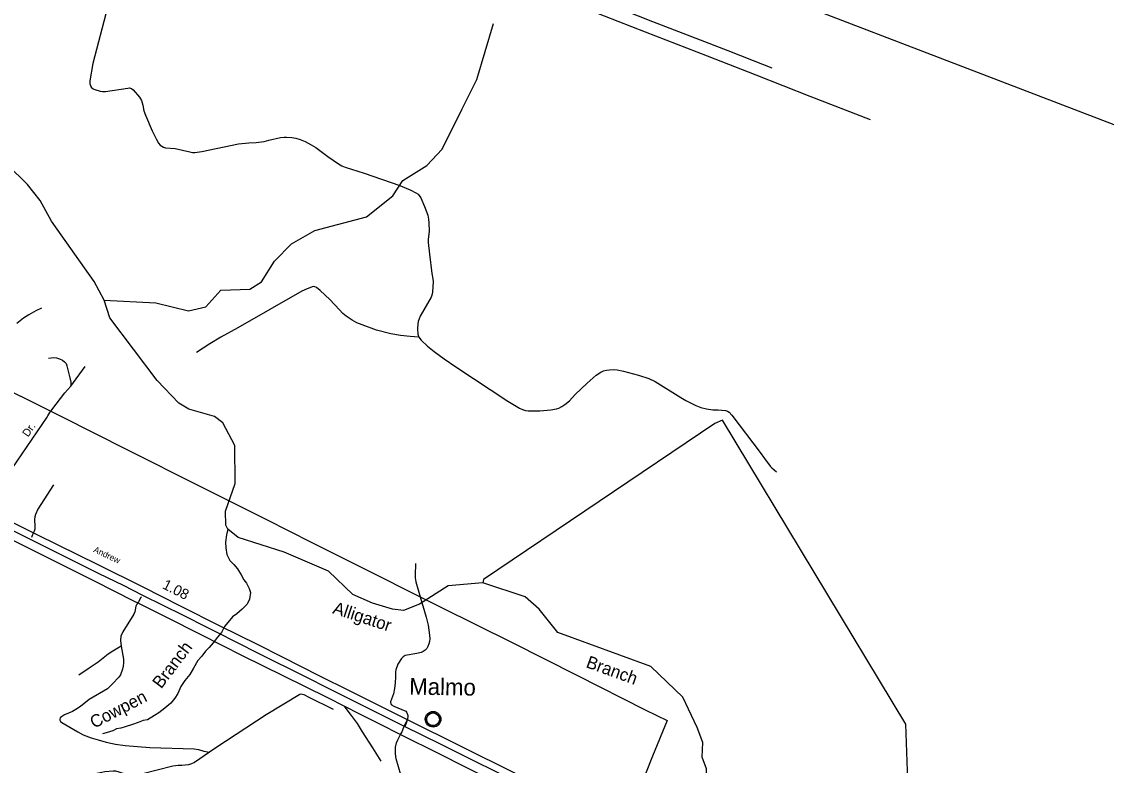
# Model space of a CAD drawing. Extents: x 2225501 to 2309677, y 165449 to 227696.
# Drawn here: x 2267922 to 2280990, y 188364 to 197321 of the extents above; entities that cross this region are included whole.
import ezdxf

# ---------------------------------------------------------------- set-up
doc = ezdxf.new("R2010")
doc.units = 0
for name, color, linetype in [('Black Area Fill Shapes', 7, 'Continuous'), ('MARK ENDS WORD SYMBOL CELL', 7, 'Continuous'), ('Old_Level_3', 7, 'Continuous'), ('Old_Level_33', 7, 'Continuous'), ('Old_Level_41', 7, 'Continuous'), ('Old_Level_46', 7, 'Continuous'), ('P_HYD_Diversion_Ditch_Label', 7, 'Continuous'), ('P_HYD_Drop_Inlet_Grate_3_Narrow_Slot_and_Sag_Grates_840_22_Type_A_60_Dia-Top_CELL', 7, 'Continuous'), ('Prop Support', 7, 'Continuous'), ('Raster_Level_0', 7, 'Continuous'), ('Scratch_Level_1', 7, 'Continuous'), ('Scratch_Level_2', 7, 'Continuous'), ('Typical Terminator CELL', 7, 'Continuous')]:
    doc.layers.add(name, color=color, linetype=linetype)

msp = doc.modelspace()

# ---------------------------------------------------------------- linework, layer by layer
at = {"layer": 'Black Area Fill Shapes'}
for points in [[(2268889, 199744), (2269360, 199561), (2269931, 199338), (2270754, 199020), (2271590, 198697), (2272090, 198499), (2272866, 198202), (2273728, 197866), (2274609, 197521), (2275433, 197198), (2276180, 196909), (2276769, 196681), (2277420, 196425), (2278147, 196143)], [(2267482, 193022), (2267541, 192993), (2268273, 192629)], [(2268273, 192629), (2268402, 192565), (2269187, 192170), (2270067, 191726), (2270870, 191325), (2271409, 191054), (2272091, 190712), (2272724, 190395)], [(2272724, 190395), (2272974, 190270), (2273833, 189844), (2274610, 189451), (2275435, 189034), (2275700, 188902)], [(2272255, 188416), (2272153, 188575), (2272027, 188769), (2271966, 188867), (2271895, 188964), (2271842, 189033), (2271812, 189075)]]:
    msp.add_lwpolyline(points, dxfattribs=at)
at = {"layer": 'Old_Level_3'}
for p, q in [((2272696, 193558), (2272708, 193522)), ((2268512, 192932), (2268686, 193169)), ((2268046, 191122), (2268040, 191107)), ((2268066, 191170), (2268046, 191122)), ((2269329, 190335), (2269320, 190322)), ((2269359, 190384), (2269329, 190335)), ((2269364, 190393), (2269359, 190384)), ((2272549, 188860), (2272540, 188839)), ((2272554, 188873), (2272549, 188860)), ((2272570, 188925), (2272554, 188873))]:
    msp.add_line(p, q, dxfattribs=at)
for points in [[(2268934, 197416), (2268780, 196819), (2268744, 196609), (2268744, 196573), (2268749, 196551), (2268760, 196532), (2268783, 196513), (2268802, 196503), (2268866, 196483), (2268896, 196479), (2268930, 196480), (2269199, 196522), (2269220, 196523), (2269245, 196517), (2269266, 196502), (2269341, 196411), (2269364, 196374), (2269381, 196316), (2269394, 196248), (2269413, 196194), (2269494, 196008), (2269542, 195909), (2269571, 195857), (2269591, 195833), (2269630, 195810), (2269654, 195802), (2269770, 195795), (2269947, 195752), (2269979, 195746), (2270009, 195747), (2270093, 195756), (2270535, 195849), (2270657, 195862), (2270747, 195868), (2270845, 195879), (2270900, 195895), (2271040, 195925), (2271084, 195931), (2271112, 195932), (2271176, 195926), (2271224, 195918), (2271278, 195903), (2271336, 195880), (2271411, 195839), (2271464, 195808), (2271612, 195699), (2271739, 195609), (2271778, 195586), (2271818, 195570), (2272047, 195498), (2272478, 195348), (2272612, 195293), (2272672, 195261), (2272698, 195242), (2272731, 195200), (2272776, 195097), (2272814, 194992), (2272825, 194941), (2272828, 194900), (2272830, 194800), (2272819, 194698), (2272820, 194662), (2272835, 194520), (2272865, 194287), (2272875, 194225), (2272878, 194187), (2272872, 194069), (2272869, 194041), (2272857, 194002), (2272723, 193776), (2272699, 193710), (2272693, 193682), (2272689, 193620), (2272696, 193558)], [(2272708, 193522), (2272601, 193529), (2272488, 193540), (2272368, 193560), (2272197, 193607), (2272023, 193668), (2271961, 193695), (2271902, 193728), (2271832, 193776), (2271793, 193808), (2271750, 193851), (2271636, 193975), (2271520, 194085), (2271472, 194118), (2271455, 194126), (2271432, 194130), (2271360, 194104), (2271299, 194075), (2270526, 193634), (2270322, 193522), (2270187, 193442), (2270027, 193337)], [(2268161, 193870), (2268092, 193839), (2268007, 193792), (2267942, 193749), (2267863, 193685)], [(2272689, 193620), (2272696, 193558)], [(2272708, 193522), (2272737, 193484), (2272810, 193414), (2272893, 193347), (2273014, 193259), (2273152, 193164), (2273780, 192752), (2273921, 192666), (2273957, 192649), (2273992, 192638), (2274026, 192633), (2274164, 192635), (2274297, 192648), (2274365, 192659), (2274393, 192667), (2274429, 192686), (2274466, 192709), (2274522, 192753), (2274592, 192829), (2274734, 192967), (2274844, 193063), (2274900, 193101), (2274933, 193115), (2274967, 193123), (2275005, 193128), (2275057, 193130), (2275095, 193126), (2275173, 193111), (2275353, 193062), (2275477, 193022), (2275554, 192988), (2275864, 192793), (2275926, 192758), (2276043, 192698), (2276103, 192675), (2276175, 192657), (2276250, 192648), (2276314, 192645), (2276402, 192637), (2276428, 192629), (2276446, 192617), (2276479, 192583), (2276819, 192132), (2276870, 192061), (2276941, 191968), (2276962, 191946), (2277015, 191901)], [(2268244, 193270), (2268308, 193277), (2268343, 193272), (2268378, 193262), (2268415, 193245), (2268437, 193225), (2268456, 193203), (2268466, 193178), (2268502, 193032), (2268512, 192981), (2268512, 192932)], [(2268273, 192629), (2268338, 192715), (2268442, 192849), (2268512, 192932)], [(2268307, 191743), (2268118, 191450), (2268087, 191385), (2268080, 191359), (2268076, 191331), (2268082, 191237), (2268079, 191209), (2268073, 191185), (2268066, 191170)], [(2272668, 190795), (2272663, 190650), (2272663, 190623), (2272672, 190575), (2272724, 190395)], [(2269320, 190322), (2269310, 190306), (2269299, 190280), (2269284, 190212), (2269275, 190186), (2269142, 189973), (2269117, 189919), (2269112, 189869), (2269121, 189801)], [(2272724, 190395), (2272795, 190147), (2272819, 190054), (2272837, 189930), (2272838, 189886), (2272836, 189856), (2272829, 189828), (2272816, 189796), (2272802, 189773), (2272784, 189753), (2272761, 189735), (2272737, 189724), (2272681, 189711), (2272541, 189687), (2272520, 189672), (2272498, 189650), (2272455, 189582), (2272428, 189515), (2272425, 189489), (2272426, 189431), (2272421, 189359), (2272412, 189290), (2272401, 189226), (2272367, 189130), (2272365, 189120), (2272368, 189104), (2272376, 189092), (2272404, 189076), (2272549, 189016), (2272557, 189005), (2272571, 188977), (2272574, 188965), (2272575, 188953), (2272570, 188925)], [(2269121, 189801), (2269148, 189644), (2269150, 189597), (2269146, 189558), (2269138, 189521), (2269111, 189455), (2269092, 189425), (2269017, 189345), (2268954, 189286), (2268734, 189158), (2268630, 189072), (2268576, 189035), (2268535, 189013), (2268437, 188971), (2268402, 188950), (2268386, 188936), (2268382, 188919), (2268383, 188906), (2268391, 188890), (2268405, 188878), (2268597, 188767), (2268664, 188733), (2268757, 188697), (2268843, 188670), (2268941, 188644), (2269054, 188620), (2269168, 188604), (2269464, 188579), (2269998, 188562), (2270051, 188553), (2270118, 188534), (2270185, 188522)], [(2269121, 189801), (2269018, 189741), (2268965, 189702), (2268844, 189606), (2268736, 189536), (2268611, 189450)], [(2271679, 189038), (2271384, 189181), (2271324, 189214), (2271287, 189221), (2271272, 189217), (2270868, 188972), (2270261, 188575), (2270185, 188522)], [(2275700, 188902), (2275521, 188473), (2275352, 188050), (2275276, 187849), (2275210, 187691), (2275178, 187620)], [(2270185, 188522), (2270002, 188399), (2269966, 188382), (2269933, 188370), (2269852, 188360), (2269806, 188361), (2269743, 188354), (2269364, 188259), (2269312, 188248), (2269271, 188244), (2269236, 188243), (2269204, 188247), (2269098, 188282), (2269058, 188292), (2269023, 188292), (2268922, 188285), (2268888, 188277), (2268768, 188255), (2268746, 188244), (2268612, 188120), (2268587, 188105), (2268464, 188053), (2268438, 188037)]]:
    msp.add_lwpolyline(points, dxfattribs=at)
at = {"layer": 'Old_Level_33'}
for points in [[(2267478, 191453), (2267564, 191588), (2268227, 192557), (2268238, 192574), (2268262, 192614), (2268273, 192629)], [(2272532, 188836), (2272571, 188913)], [(2272490, 188251), (2272432, 188444), (2272426, 188504), (2272427, 188583), (2272438, 188635), (2272452, 188671), (2272488, 188734)], [(2272488, 188734), (2272502, 188758), (2272532, 188836)]]:
    msp.add_lwpolyline(points, dxfattribs=at)
at = {"layer": 'Old_Level_41'}
for points in [[(2267396, 200499), (2268070, 200237), (2268534, 200054), (2268881, 199922), (2269170, 199812), (2269667, 199615), (2270286, 199376), (2270713, 199209), (2271139, 199044), (2271663, 198840), (2272166, 198644), (2272574, 198485), (2272905, 198353), (2273403, 198161), (2273753, 198023), (2274386, 197776), (2275025, 197521), (2275521, 197325), (2276043, 197125), (2276429, 196975), (2276734, 196855), (2276961, 196766)], [(2267760, 191104), (2268233, 190867), (2268796, 190586), (2269277, 190343), (2269320, 190322), (2269657, 190154), (2270082, 189939), (2270587, 189684), (2271069, 189444), (2271606, 189179), (2271812, 189075), (2271991, 188985), (2272232, 188862), (2272488, 188734)], [(2272488, 188734), (2272520, 188719), (2272922, 188518), (2273282, 188336), (2273777, 188087), (2274197, 187876), (2274622, 187659), (2275028, 187454), (2275340, 187296), (2275646, 187143), (2275867, 187032), (2276038, 186946), (2276485, 186723), (2276552, 186689), (2277052, 186436), (2277565, 186176), (2278026, 185945), (2278424, 185743), (2278532, 185693)]]:
    msp.add_lwpolyline(points, dxfattribs=at)
at = {"layer": 'Old_Level_46'}
for points in [[(2267446, 191381), (2267549, 191323), (2268023, 191089), (2268853, 190675), (2269145, 190533), (2269376, 190413), (2269867, 190171), (2270152, 190029), (2270264, 189970), (2270773, 189716), (2271345, 189429), (2271616, 189294), (2272532, 188836)], [(2272571, 188913), (2271872, 189261), (2271516, 189439), (2271065, 189667), (2270762, 189820), (2270313, 190042), (2269837, 190283), (2269384, 190510), (2268843, 190777), (2268116, 191138), (2267673, 191357), (2267478, 191453)], [(2280362, 186265), (2280231, 186273), (2279701, 186313), (2279516, 186324), (2279339, 186336), (2279057, 186354), (2278721, 186383), (2278222, 186413), (2277849, 186444), (2277690, 186462), (2277556, 186485), (2277450, 186513), (2277362, 186540), (2277250, 186589), (2277073, 186664), (2276912, 186748), (2276736, 186835), (2276186, 187108), (2275430, 187486), (2275000, 187700), (2273873, 188264), (2272571, 188913)], [(2272532, 188836), (2272972, 188618), (2274019, 188097), (2274464, 187872), (2274957, 187623), (2275911, 187143), (2276095, 187047), (2276229, 186984), (2276596, 186805), (2277156, 186523), (2277270, 186476), (2277395, 186438), (2277499, 186405), (2277635, 186381), (2277841, 186354), (2278381, 186315), (2278609, 186299), (2278740, 186290), (2278980, 186279), (2279269, 186254), (2279551, 186230), (2279747, 186216), (2279890, 186205)]]:
    msp.add_lwpolyline(points, dxfattribs=at)
at = {"layer": 'P_HYD_Diversion_Ditch_Label'}
msp.add_lwpolyline([(2272801, 188931), (2272802, 188937), (2272804, 188943), (2272807, 188951), (2272810, 188956), (2272813, 188962), (2272817, 188967), (2272821, 188972), (2272826, 188976), (2272831, 188981), (2272837, 188985), (2272841, 188987), (2272846, 188990), (2272852, 188992), (2272858, 188994), (2272862, 188995), (2272867, 188996), (2272871, 188997), (2272877, 188997), (2272882, 188997), (2272887, 188996), (2272892, 188996), (2272897, 188995), (2272902, 188993), (2272907, 188991), (2272914, 188988), (2272920, 188985), (2272925, 188981), (2272930, 188977), (2272934, 188974), (2272938, 188970), (2272942, 188965), (2272945, 188961), (2272948, 188956), (2272950, 188950), (2272952, 188945), (2272954, 188940), (2272955, 188936), (2272956, 188930), (2272957, 188925), (2272957, 188919), (2272957, 188913), (2272957, 188908), (2272956, 188902), (2272954, 188896), (2272952, 188890), (2272950, 188885), (2272947, 188879), (2272943, 188874), (2272940, 188869), (2272936, 188864), (2272930, 188859), (2272925, 188855), (2272920, 188852), (2272916, 188849), (2272909, 188846), (2272902, 188843), (2272896, 188842), (2272890, 188841), (2272885, 188840), (2272881, 188840), (2272875, 188840), (2272871, 188840), (2272865, 188841), (2272859, 188842), (2272855, 188844), (2272849, 188845), (2272845, 188847), (2272841, 188850), (2272834, 188854), (2272829, 188858), (2272824, 188863), (2272819, 188867), (2272816, 188871), (2272813, 188876), (2272809, 188883), (2272807, 188886), (2272805, 188890), (2272803, 188898), (2272801, 188905), (2272801, 188911), (2272800, 188917), (2272800, 188922), (2272801, 188928)], close=True, dxfattribs=at)
for radius in [94.3, 76.7]:
    msp.add_circle((2272879, 188919), radius, dxfattribs=at)
at = {"layer": 'Prop Support'}
for points in [[(2284408, 194805), (2272002, 199563), (2267570, 201312)], [(2277052, 186964), (2278609, 187846), (2278575, 188860), (2276366, 192521), (2276275, 192480), (2273485, 190602), (2273477, 190563)]]:
    msp.add_lwpolyline(points, dxfattribs=at)
at = {"layer": 'Typical Terminator CELL'}
for points in [[(2268914, 193968), (2269539, 193933), (2269931, 193837), (2270139, 193888), (2270321, 194088), (2270670, 194101), (2270811, 194187), (2270967, 194436), (2271173, 194646), (2271455, 194807), (2272078, 194972), (2272392, 195225), (2272516, 195410), (2272805, 195588), (2272987, 195788), (2273224, 196265), (2273404, 196626), (2273605, 197301)], [(2268914, 193968), (2268795, 194190), (2268280, 194918), (2268145, 195167), (2267993, 195360), (2267749, 195598), (2267573, 195729), (2267505, 195911), (2267420, 196011), (2266959, 196289)], [(2270406, 191207), (2270380, 191256), (2270379, 191424), (2270492, 191759), (2270488, 192215), (2270344, 192490), (2270243, 192565), (2269934, 192653), (2269817, 192727), (2269556, 192998), (2268983, 193753), (2268914, 193968)], [(2270406, 191207), (2270388, 191140), (2270379, 191053), (2270382, 190985), (2270395, 190904), (2270429, 190833), (2270479, 190784), (2270522, 190732), (2270566, 190660), (2270600, 190600), (2270630, 190557), (2270664, 190493), (2270678, 190446), (2270667, 190367), (2270638, 190307), (2270579, 190246), (2270514, 190188), (2270460, 190151), (2270366, 190035), (2270330, 189965), (2270281, 189906), (2270229, 189841), (2270182, 189783), (2270138, 189740), (2270094, 189680), (2270044, 189625), (2269993, 189536), (2269948, 189457), (2269887, 189385), (2269841, 189315), (2269802, 189230), (2269767, 189172), (2269718, 189111), (2269647, 189051), (2269574, 188997), (2269520, 188964), (2269437, 188911), (2269387, 188903), (2269325, 188879), (2269256, 188855), (2269169, 188829), (2269116, 188812), (2269064, 188805), (2269018, 188780), (2268978, 188766), (2268941, 188754), (2268895, 188745)], [(2273477, 190563), (2273061, 190525), (2272713, 190306), (2272523, 190227), (2272389, 190243), (2272147, 190317), (2271913, 190423), (2271619, 190704), (2271083, 190931), (2270532, 191109), (2270406, 191207)], [(2277052, 186964), (2276924, 187213), (2276739, 187377), (2276221, 187623), (2276186, 187755), (2276172, 188323), (2276121, 188462), (2276128, 188639), (2276059, 188820), (2275889, 189185), (2275503, 189556), (2274383, 189962), (2274155, 190245), (2273987, 190392), (2273477, 190563)]]:
    msp.add_lwpolyline(points, dxfattribs=at)

# ---------------------------------------------------------------- texts
at = {"layer": 'MARK ENDS WORD SYMBOL CELL'}
msp.add_text('Dr.', height=95, rotation=55.6168, dxfattribs=at).set_placement((2267999, 192312))
at = {"layer": 'P_HYD_Drop_Inlet_Grate_3_Narrow_Slot_and_Sag_Grates_840_22_Type_A_60_Dia-Top_CELL'}
msp.add_text('Malmo', height=200, rotation=359.0674, dxfattribs=at).set_placement((2272590, 189216))
at = {"layer": 'Raster_Level_0'}
msp.add_text('1.08', height=125, rotation=333.2291, dxfattribs=at).set_placement((2269607, 190500))
at = {"layer": 'Scratch_Level_1'}
for s, rotation, p in [('Alligator', 341.9575, (2271659, 190197)), ('Branch', 52.8197, (2269603, 189278)), ('Branch', 340.0939, (2274711, 189548)), ('Cowpen', 27.4192, (2268793, 188804))]:
    msp.add_text(s, height=150, rotation=rotation, dxfattribs=at).set_placement(p)
at = {"layer": 'Scratch_Level_2'}
msp.add_text('Andrew', height=75, rotation=334.474, dxfattribs=at).set_placement((2268780, 190937))

doc.saveas('drawing.dxf')
